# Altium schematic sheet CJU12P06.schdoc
size 127 x 101 mm
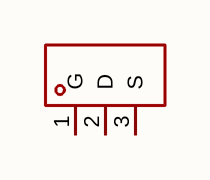
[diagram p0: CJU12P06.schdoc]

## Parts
Q?  cju12p06  [TO-252-2_L6.6-W6.1-P4.57-LS10.0-BR-1]  (value not drawn)

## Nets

Not connected (* = marked no-connect by the designer): Q? 1(G) 2(D) 3(S)

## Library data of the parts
Q? = cju12p06: 数量:1个P沟道;漏源电压(Vdss):60V;连续漏极电流(Id):12A;导通电阻(RDS(on)):96mΩ@10V;耗散功率(Pd):50W;阈值电压(Vgs(th)):3V;; Manufacturer: CJ(江苏长电/长晶); AddInBom: yes; ModelId: 4113ec4a058842b08e2585e7304bd9b4; ModelTransform: 401.574,259.842,0,0,0,0,-36.417,0,0; Number: 1个P沟道; Drain to Source Voltage: 60V; Current - Continuous Drain(Id): 12A; Pd - Power Dissipation: 50W; Gate Threshold Voltage (Vgs(th)): 3V; Gate Charge(Qg): 35nC@10V; Input Capacitance(Ciss): 1.6nF; Reverse Transfer Capacitance (Crss@Vds): 78pF; Type: P沟道; Output Capacitance(Coss): 200pF; Vgs: ±20V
